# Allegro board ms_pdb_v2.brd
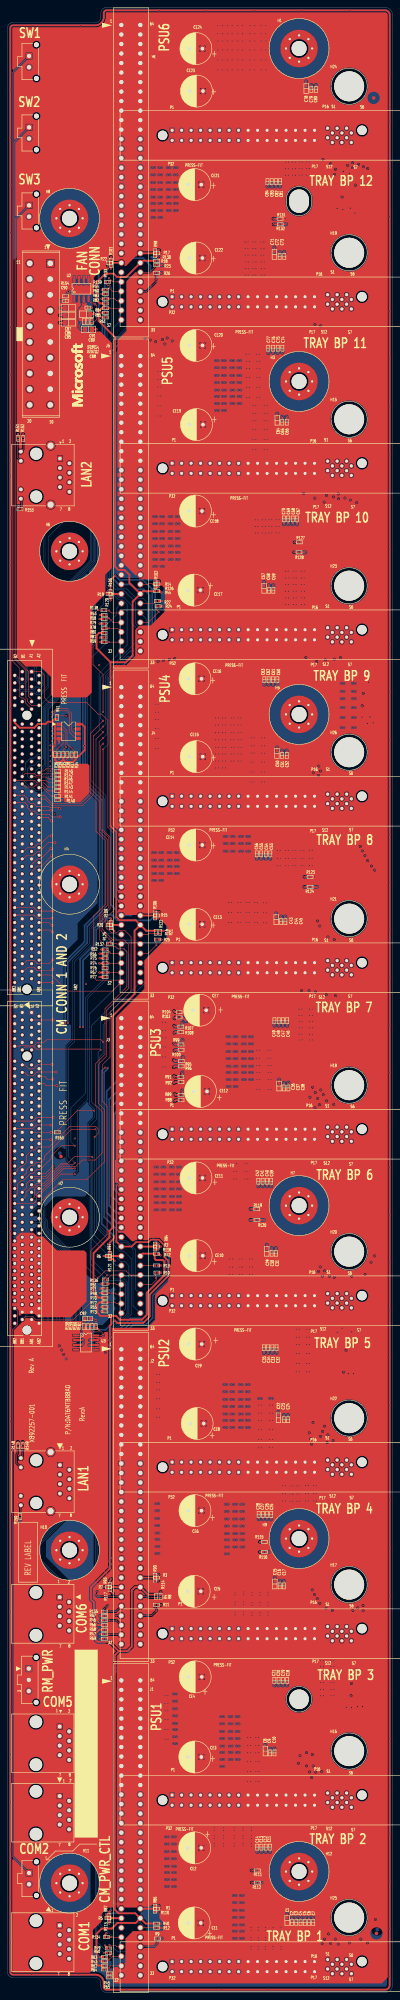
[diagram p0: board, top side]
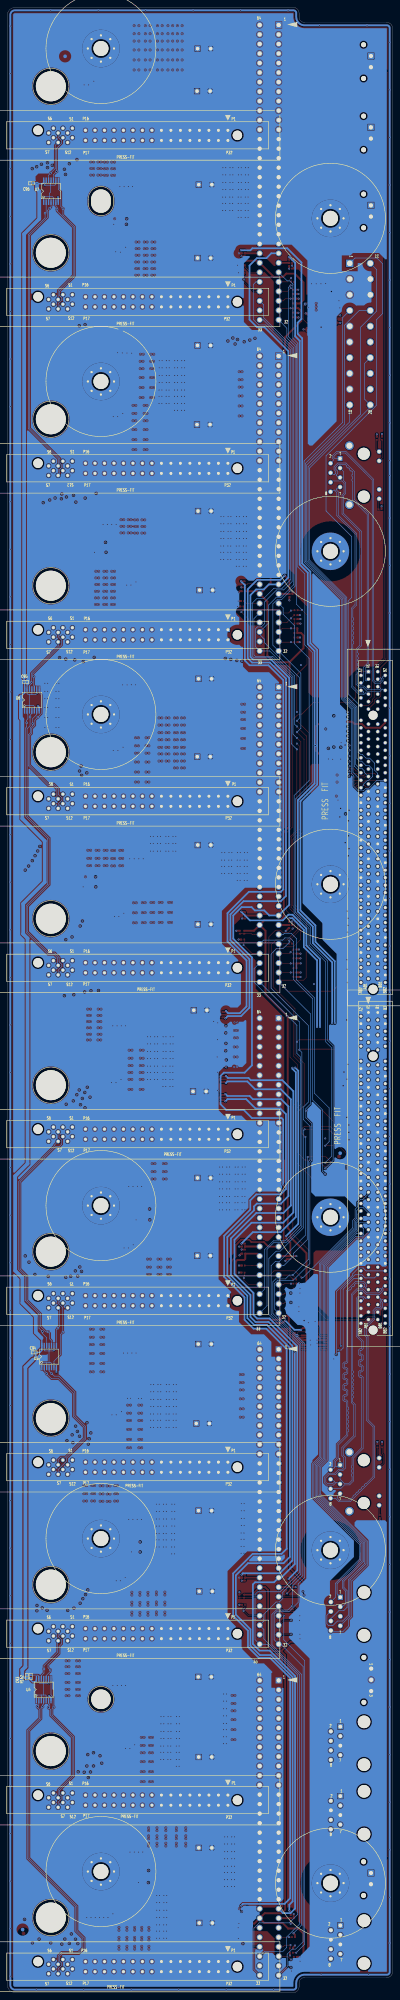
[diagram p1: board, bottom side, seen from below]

Outline 103 x 530 mm; copper layers: TOP, GND, IN1, VCC, VCC1, IN2, GND1, BOTTOM. Coordinates in mm from the lower left corner of the outline.
Outline path: 0,524.5 0,5.5 arc(0.44,4.44) 1.5,4 23.5,4 arc(24.56,3.56) 25,2.5 25,1.5 arc(25.44,0.44) 26.5,0 101,0 arc(102.41,0.59) 103,2 103,528 arc(102.41,529.41) 101,530 26.5,530 arc(25.44,529.56) 25,528.5 25,527.5 arc(24.56,526.44) 23.5,526 1.5,526 arc(0.44,525.56) 0,524.5 ; 75.4,478.8 arc(78,481.4) 80.6,478.8 80.6,477.8 arc(78,475.2) 75.4,477.8 75.4,478.8

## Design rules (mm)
net group LAN: nets LAN1_P1_P LAN1_P2_P LAN1_P4_N LAN1_P4_P
net group SMB: nets I2C_PDB_SCL I2C_PDB_SDA I2C_PSU1_SCL I2C_PSU1_SDA I2C_PSU2_SCL I2C_PSU2_SDA I2C_PSU3_SCL I2C_PSU3_SDA
net group UART: nets UART_CTS_P1_L_N UART_CTS_P2_L_N UART_CTS_P5_L_N UART_CTS_P6_L_N UART_DSR_P1_L_N UART_DSR_P2_L_N UART_DTR_P1_L_N UART_DTR_P2_L_N UART_DTR_P5_L_N UART_DTR_P6_L_N UART_RI_P5_L_N UART_RI_P6_L_N UART_RTS_P1_L_N UART_RTS_P2_L_N UART_RTS_P5_L_N UART_RTS_P6_L_N UART_RX_P1_L UART_RX_P2_L UART_RX_P5_L UART_RX_P6_L UART_TX_P1_L UART_TX_P2_L UART_TX_P5_L UART_TX_P6_L

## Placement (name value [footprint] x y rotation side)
C1  1UF  [C0603]  74.8 19.26 270 top
C2  0.1UF  [C0402]  76.12 18.75 270 top
C3  0.1UF  [C0402]  77.25 18.75 270 top
C4  0.1UF  [C0402]  78.4 18.75 270 top
C5  0.1UF  [C0402]  79.52 18.75 270 top
C6  0.1UF  [C0402]  80.66 18.75 270 top
C7  100PF  [C0402]  81.79 18.75 270 top
C8  1UF  [C0603]  68.97 64.48 270 top
C9  0.1UF  [C0402]  70.26 63.97 270 top
C10  0.1UF  [C0402]  71.42 63.97 270 top
C11  0.1UF  [C0402]  70.24 38.82 90 top
C12  0.1UF  [C0402]  69.07 38.82 90 top
C13  0.1UF  [C0402]  67.92 38.82 90 top
C14  100PF  [C0402]  66.82 38.82 90 top
C15  1UF  [C0603]  71.52 109.08 270 top
C16  0.1UF  [C0402]  72.81 108.57 270 top
C17  0.1UF  [C0402]  73.91 108.57 270 top
C18  0.1UF  [C0402]  74.8 83.34 90 top
C19  0.1UF  [C0402]  73.63 83.34 90 top
C20  0.1UF  [C0402]  72.52 83.34 90 top
C21  100PF  [C0402]  71.39 83.34 90 top
C22  1UF  [C0603]  72.48 153.43 270 top
C23  0.1UF  [C0402]  73.91 152.92 270 top
C24  0.1UF  [C0402]  75.06 152.92 270 top
C25  0.1UF  [C0402]  70.56 127.63 90 top
C26  0.1UF  [C0402]  69.44 127.63 90 top
C27  0.1UF  [C0402]  68.31 127.63 90 top
C28  100PF  [C0402]  67.19 127.63 90 top
C29  1UF  [C0603]  69.37 197.9 270 top
C30  0.1UF  [C0402]  70.66 197.39 270 top
C31  0.1UF  [C0402]  71.82 197.39 270 top
C32  0.1UF  [C0402]  71.97 172.14 90 top
C33  0.1UF  [C0402]  70.85 172.14 90 top
C34  0.1UF  [C0402]  69.73 172.14 90 top
C35  100PF  [C0402]  68.61 172.14 90 top
C36  1UF  [C0603]  72.64 242.03 270 top
C37  0.1UF  [C0402]  73.96 241.52 270 top
C38  0.1UF  [C0402]  75.15 241.52 270 top
C39  0.1UF  [C0402]  70.56 216.62 90 top
C40  0.1UF  [C0402]  69.42 216.62 90 top
C41  0.1UF  [C0402]  68.25 216.62 90 top
C42  100PF  [C0402]  67.1 216.62 90 top
C43  1UF  [C0603]  71.87 286.47 270 top
C44  0.1UF  [C0402]  73.2 285.97 270 top
C45  0.1UF  [C0402]  74.35 285.97 270 top
C46  0.1UF  [C0402]  74.83 259.45 90 top
C47  0.1UF  [C0402]  73.69 259.45 90 top
C48  0.1UF  [C0402]  72.56 259.45 90 top
C49  100PF  [C0402]  71.41 259.45 90 top
C50  1UF  [C0603]  72.09 330.84 270 top
C51  0.1UF  [C0402]  73.46 330.33 270 top
C52  0.1UF  [C0402]  74.71 330.33 270 top
C53  0.1UF  [C0402]  70.31 304.01 90 top
C54  0.1UF  [C0402]  69.11 304.01 90 top
C55  0.1UF  [C0402]  67.87 304.01 90 top
C56  100PF  [C0402]  66.69 304.01 90 top
C57  1UF  [C0603]  68.64 374.92 270 top
C58  0.1UF  [C0402]  69.98 374.41 270 top
C59  0.1UF  [C0402]  71.12 374.41 270 top
C60  0.1UF  [C0402]  72.2 350.5 90 top
C61  0.1UF  [C0402]  71 350.5 90 top
C62  0.1UF  [C0402]  69.86 350.5 90 top
C63  100PF  [C0402]  68.73 350.5 90 top
C64  1UF  [C0603]  72.16 419.8 270 top
C65  0.1UF  [C0402]  73.51 419.29 270 top
C66  0.1UF  [C0402]  74.7 419.29 270 top
C67  0.1UF  [C0402]  77.44 393.45 90 top
C68  0.1UF  [C0402]  76.3 393.45 90 top
C69  0.1UF  [C0402]  75.1 393.45 90 top
C70  100PF  [C0402]  73.93 393.45 90 top
C71  1UF  [C0603]  71.39 464.05 270 top
C72  0.1UF  [C0402]  72.8 463.54 270 top
C73  0.1UF  [C0402]  74.05 463.54 270 top
C74  0.1UF  [C0402]  73.53 439.04 90 top
C75  0.1UF  [C0402]  72.28 439.04 90 top
C76  0.1UF  [C0402]  71.04 439.04 90 top
C77  100PF  [C0402]  69.77 439.04 90 top
C78  1UF  [C0603]  79.9 508.38 270 top
C79  0.1UF  [C0402]  81.29 508.12 270 top
C80  0.1UF  [C0402]  82.5 508.12 270 top
C81  0.1UF  [C0402]  72.93 483.48 90 top
C82  0.1UF  [C0402]  71.81 483.48 90 top
C83  0.1UF  [C0402]  70.68 483.48 90 top
C84  100PF  [C0402]  69.55 483.48 90 top
C85  10UF  [C0805_H61]  16.26 445.81 0 top
C86  10UF  [C0805_H61]  16.26 447.8 0 top
C87  10UF  [C0805_H61]  16.26 449.79 0 top
C88  10UF  [C0805_H61]  21.67 444.05 180 top
C89  10UF  [C0805_H61]  21.16 448.1 180 top
C90  0.1UF  [C0402]  15.54 451.71 0 top
C91  0.1UF  [C0402]  21.51 449.86 180 top
C92  2.2UF  [C0603]  21.45 179.96 0 top
C93  0.1UF  [C0402]  97.83 84.36 270 bottom
C94  0.1UF  [C0402]  95.87 170.92 180 bottom
C95  0.1UF  [C0402]  98.16 349.95 0 bottom
C96  0.1UF  [C0402]  96.61 483.04 180 bottom
CE1  470UF  [EC138_315_433]  49.95 18.57 180 top
CE2  470UF  [EC138_315_433]  50.08 38.62 180 top
CE3  470UF  [EC138_315_433]  50.1 62.88 180 top
CE4  470UF  [EC138_315_433]  50.22 84.27 180 top
CE5  470UF  [EC138_315_433]  49.95 107.12 180 top
CE6  470UF  [EC138_315_433]  50.15 128.66 180 top
CE7  470UF  [EC138_315_433]  51.41 262.27 180 top
CE8  470UF  [EC138_315_433]  50.74 151.93 180 top
CE9  470UF  [EC138_315_433]  50.22 173.14 180 top
CE10  470UF  [EC138_315_433]  50.48 196.73 180 top
CE11  470UF  [EC138_315_433]  50.42 217.49 180 top
CE12  470UF  [EC138_315_433]  51.61 240.59 180 top
CE13  470UF  [EC138_315_433]  50.33 285.21 180 top
CE14  470UF  [EC138_315_433]  50.35 306.38 180 top
CE15  470UF  [EC138_315_433]  50.48 329.97 180 top
CE16  470UF  [EC138_315_433]  50.15 350.77 180 top
CE17  470UF  [EC138_315_433]  49.87 374.44 180 top
CE18  470UF  [EC138_315_433]  50.28 395.55 180 top
CE19  470UF  [EC138_315_433]  50.55 418.64 180 top
CE20  470UF  [EC138_315_433]  50.42 439.76 180 top
CE21  470UF  [EC138_315_433]  50.08 482.71 180 top
CE22  470UF  [EC138_315_433]  50.4 463.1 180 top
CE23  470UF  [EC138_315_433]  50.55 507.68 180 top
CE24  470UF  [EC138_315_433]  50.4 519.02 180 top
H1  GNDHOLE_8PIN  [GND_C10D4B10]  78 519.05 0 top
H2  GNDHOLE_8PIN  [GND_C10D4B10]  16.6 207 0 top
H3  GNDHOLE_8PIN  [GND_C10D4B10]  78 430.15 0 top
H4  GNDHOLE_8PIN  [GND_C10D4B10]  16.6 295.9 0 top
H5  GNDHOLE_8PIN  [GND_C10D4B10]  78 341.25 0 top
H6  GNDHOLE_8PIN  [GND_C10D4B10]  16.6 384.8 0 top
H7  GNDHOLE_8PIN  [GND_C10D4B10]  78 210.1 0 top
H8  GNDHOLE_8PIN  [GND_C10D4B10]  16.6 473.7 0 top
H9  GNDHOLE_8PIN  [GND_C10D4B10]  78 121.2 0 top
H10  GNDHOLE_8PIN  [GND_C10D4B10]  16.6 118.1 0 top
H11  GNDHOLE_8PIN  [GND_C10D4B10]  16.6 29.2 0 top
H12  GNDHOLE_8PIN  [GND_C10D4B10]  78 32.3 0 top
H13  -  [HOLE_OB5-2X6-2N]  78 478.3 0 top
H14  -  [HOLE_D5-2N]  78 78.3 0 top
H15  D8N  [HOLE_D8N]  91.4 420.06 0 top
H16  D8N  [HOLE_D8N]  91.4 64.46 0 top
H17  D8N  [HOLE_D8N]  91.4 108.91 0 top
H18  D8N  [HOLE_D8N]  91.4 242.26 0 top
H19  D8N  [HOLE_D8N]  91.4 464.51 0 top
H20  D8N  [HOLE_D8N]  91.4 197.81 0 top
H21  D8N  [HOLE_D8N]  91.4 286.71 0 top
H22  D8N  [HOLE_D8N]  91.4 153.36 0 top
H23  D8N  [HOLE_D8N]  91.4 375.61 0 top
H24  D8N  [HOLE_D8N]  91.4 508.96 0 top
H25  D8N  [HOLE_D8N]  91.4 20.01 0 top
H26  D8N  [HOLE_D8N]  91.4 331.16 0 top
J1  10046971-001LF  [CON_64D2_P2-54_LDH]  30.46 83.33 0 top
J2  10046971-001LF  [CON_64D2_P2-54_LDH]  30.46 171.73 0 top
J3  10046971-001LF  [CON_64D2_P2-54_LDH]  30.46 260.13 0 top
J4  10046971-001LF  [CON_64D2_P2-54_LDH]  30.46 348.53 0 top
J5  10046971-001LF  [CON_64D2_P2-54_LDH]  30.46 436.93 0 top
J6  10046971-001LF  [CON_64D2_P2-54_LDH]  30.46 525.33 0 top
J7  CONN44_10117936003LF  [HSD_44D2H2D_P2-54_LDH]  44.04 8.26 270 bottom
J8  CONN44_10117936003LF  [HSD_44D2H2D_P2-54_LDH]  44.04 52.71 270 bottom
J9  CONN44_10117936003LF  [HSD_44D2H2D_P2-54_LDH]  44.04 97.16 270 bottom
J10  CONN44_10117936003LF  [HSD_44D2H2D_P2-54_LDH]  44.04 141.61 270 bottom
J11  CONN44_10117936003LF  [HSD_44D2H2D_P2-54_LDH]  44.04 186.06 270 bottom
J12  CONN44_10117936003LF  [HSD_44D2H2D_P2-54_LDH]  44.04 230.51 270 bottom
J13  CONN44_10117936003LF  [HSD_44D2H2D_P2-54_LDH]  44.04 274.96 270 bottom
J14  CONN44_10117936003LF  [HSD_44D2H2D_P2-54_LDH]  44.04 319.41 270 bottom
J15  CONN44_10117936003LF  [HSD_44D2H2D_P2-54_LDH]  44.04 363.86 270 bottom
J16  CONN44_10117936003LF  [HSD_44D2H2D_P2-54_LDH]  44.04 408.31 270 bottom
J17  CONN44_10117936003LF  [HSD_44D2H2D_P2-54_LDH]  44.04 452.76 270 bottom
J18  CONN44_10117936003LF  [HSD_44D2H2D_P2-54_LDH]  44.04 497.21 270 bottom
J19  CONN8_55692841  [RJ45XBT]  13.96 17.91 270 top
J20  CONN20_39281203  [CON_PWR2X10XD]  11.44 461.69 0 top
J21  CONN8_55692841  [RJ45XBT]  13.96 52.45 270 top
J23  CONN8_55692841  [RJ45XBT]  13.96 70.99 270 top
J25  PCIEX16  [HSD_PCI-E_X16XA]  6.45 352.67 0 top
J26  PCIEX16  [HSD_PCI-E_X16XA]  6.45 261.67 0 top
J27  CONN8_55692841  [RJ45XBT]  13.96 105.54 270 top
J28  CONN12_G71B0250100EU  [RJ45XBU]  14.03 409.58 270 top
J29  CONN12_G71B0250100EU  [RJ45XBU]  14.03 140.84 270 top
J30  CONN2_43650-0217  [CON_2D1H2D_P3XA]  5.78 477.17 0 top
J31  CONN2_43650-0217  [CON_2D1H2D_P3XA]  5.78 498 0 top
J32  CONN2_43650-0217  [CON_2D1H2D_P3XA]  5.78 517.05 0 top
J33  CONN2_43650-0217  [CON_2D1H2D_P3XA]  5.78 31.91 0 top
J34  CONN3_43650-0317  [CON_3D1H2D_P3]  5.71 86.48 0 top
NOREF  -  []  41.5 495.86 0 top
NOREF#2  -  []  5.78 31.91 0 top
NOREF#3  -  []  91.4 242.26 0 top
NOREF#4  -  []  16.6 473.7 0 top
NOREF#5  -  []  -111 530 0 top
NOREF#6  -  []  91.4 64.46 0 top
NOREF#7  -  []  41.5 495.86 0 top
NOREF#8  -  []  94.84 452.76 0 top
NOREF#9  -  []  94.84 408.31 0 top
NOREF#10  -  []  -105 528 0 top
NOREF#11  -  []  16.6 384.8 0 top
NOREF#12  -  []  91.4 153.36 0 top
NOREF#13  -  []  -1 197.97 90 top
NOREF#14  -  []  101 0 90 top
NOREF#15  -  []  210.46 461.17 0 top
NOREF#16  -  []  94.84 230.51 0 top
NOREF#17  -  []  41.5 451.41 0 top
NOREF#18  -  []  94.84 274.96 0 top
NOREF#19  -  []  94.84 497.21 0 top
NOREF#20  -  []  -1 114.98 90 top
NOREF#21  -  [unnamed#2]  98.7 15.77 0 top
NOREF#22  -  []  91.4 197.81 0 top
NOREF#23  -  []  -1 32.01 90 top
NOREF#24  -  []  -1 239.48 90 top
NOREF#25  -  []  41.5 140.26 0 top
NOREF#26  -  []  16.6 29.2 0 top
NOREF#27  -  []  7.99 109.56 90 top
NOREF#28  -  []  41.5 184.71 0 top
NOREF#29  -  []  14.03 140.84 0 top
NOREF#30  -  []  13.96 105.54 0 top
NOREF#31  -  []  13.96 105.54 0 top
NOREF#32  -  []  78 519.05 0 top
NOREF#33  -  []  16.6 118.1 0 top
NOREF#34  -  []  91.4 20.01 0 top
NOREF#35  -  [unnamed#2]  14.31 223.21 0 top
NOREF#36  -  []  5.2 341.02 0 top
NOREF#37  -  []  78 478.3 0 top
NOREF#38  -  []  41.5 229.16 0 top
NOREF#39  -  []  16.6 295.9 0 top
NOREF#40  -  []  0 0 0 top
NOREF#41  -  []  41.5 6.91 0 top
NOREF#42  -  []  41.5 273.61 0 top
NOREF#43  -  []  79.57 480.38 0 top
NOREF#44  -  []  78 32.3 0 top
NOREF#45  -  []  -1 73.51 90 top
NOREF#46  -  []  91.4 420.06 0 top
NOREF#47  -  []  13.96 52.45 0 top
NOREF#48  -  []  16.6 473.7 0 top
NOREF#49  -  []  0 529.34 0 top
NOREF#50  -  []  13.96 70.99 0 top
NOREF#51  -  []  91.4 464.51 0 top
NOREF#52  -  []  -1 280.95 90 top
NOREF#53  -  []  11.44 461.69 0 top
NOREF#54  -  []  5.78 498 0 top
NOREF#55  -  []  41.5 362.51 0 top
NOREF#56  -  []  91.4 331.16 0 top
NOREF#57  -  []  -1 449.46 90 top
NOREF#58  -  []  25 528.5 0 top
NOREF#59  -  []  94.84 141.61 0 top
NOREF#60  -  []  162.67 -30.28 0 top
NOREF#61  -  []  94.84 97.16 0 top
NOREF#62  -  []  41.5 51.36 0 top
NOREF#63  -  []  -1 498.02 90 top
NOREF#64  -  []  94.84 497.21 0 top
NOREF#65  -  []  13.96 17.91 0 top
NOREF#66  -  []  -1 156.49 90 top
NOREF#67  -  []  41.5 95.81 0 top
NOREF#68  -  []  78 341.25 0 top
NOREF#69  -  []  5.78 517.05 0 top
NOREF#70  -  []  78 210.1 0 top
NOREF#71  -  []  20.1 423.59 90 top
NOREF#72  -  []  94.84 363.86 0 top
NOREF#73  -  []  -1 366.48 90 top
NOREF#74  -  []  78 519.05 0 top
NOREF#75  -  []  78 430.15 0 top
NOREF#76  -  []  41.5 406.96 0 top
NOREF#77  -  []  94.84 8.26 0 top
NOREF#78  -  []  91.4 508.96 0 top
NOREF#79  -  []  41.5 318.06 0 top
NOREF#80  -  []  16.6 207 0 top
NOREF#81  -  []  5.2 267.87 0 top
NOREF#82  -  []  91.4 508.96 0 top
NOREF#83  -  []  94 78.3 0 top
NOREF#84  -  []  0 0 0 top
NOREF#85  -  []  91.4 108.91 0 top
NOREF#86  -  []  5.2 341.02 0 top
NOREF#87  -  []  21.04 66.46 90 top
NOREF#88  -  []  94.84 186.06 0 top
NOREF#89  -  []  5.78 477.17 0 top
NOREF#90  -  []  78 121.2 0 top
NOREF#91  -  []  103 528 0 top
NOREF#92  -  []  -1 407.95 90 top
NOREF#93  -  []  -26.94 745.4 0 top
NOREF#94  -  []  91.4 375.61 0 top
NOREF#95  -  []  5.71 86.48 0 top
NOREF#96  -  []  94.84 52.71 0 top
NOREF#97  -  []  11.44 461.69 0 top
NOREF#98  -  []  14.03 409.58 0 top
NOREF#99  -  []  94.84 319.41 0 top
NOREF#100  -  []  14.03 140.84 0 top
NOREF#101  -  []  13.96 105.54 0 top
NOREF#102  -  [unnamed#2]  97.95 505.86 0 top
NOREF#103  -  []  -23.4 0 90 top
NOREF#104  -  []  91.4 286.71 0 top
NOREF#105  -  []  -1 322.46 90 top
NOREF#106  -  []  5.78 517.05 0 top
NOREF#107  -  []  0 0 0 top
NOREF#108  -  [unnamed#2]  98.95 16.81 180 bottom
NOREF#109  -  [unnamed#2]  14.01 224.1 180 bottom
NOREF#110  -  [unnamed#2]  87.59 516.96 180 bottom
R1  0  [R0402]  39.87 22.38 180 top
R2  0  [R0402]  39.86 199.17 180 top
R3  0  [R0402]  39.86 110.77 180 top
R4  22.1K  [R0402]  39.71 105.82 270 top
R5  0  [R0402]  26.85 19.86 0 top
R6  0  [R0402]  26.93 196.62 0 top
R7  0  [R0402]  26.95 108.23 0 top
R8  8.2K  [R0402]  40.96 105.82 270 top
R9  100  [R0402]  40.16 14.41 180 top
R10  100  [R0402]  39.97 192.22 180 top
R11  100  [R0402]  39.86 103.52 180 top
R12  100  [R0402]  39.85 17.31 180 top
R13  100  [R0402]  39.9 194.11 180 top
R14  0  [R0402]  39.98 375.99 180 top
R15  0  [R0402]  39.86 287.57 180 top
R16  22.1K  [R0402]  39.65 283.1 270 top
R17  0  [R0402]  39.94 464.37 180 top
R18  22.1K  [R0402]  39.87 462.37 0 top
R19  0  [R0402]  27.17 373.43 0 top
R20  0  [R0402]  27.24 285.03 0 top
R21  8.2K  [R0402]  40.86 283.1 270 top
R22  0  [R0402]  27.24 461.83 0 top
R23  8.2K  [R0402]  39.87 461.17 180 top
R24  100  [R0402]  40.3 370.1 180 top
R25  100  [R0402]  40.06 281.14 180 top
R26  100  [R0402]  39.95 459.17 180 top
R27  100  [R0402]  40.11 371.51 180 top
R34  3.3K  [R0402]  18.26 330.46 270 top
R35  3.3K  [R0402]  14.92 330.5 270 top
R36  3.3K  [R0402]  12.78 330.48 270 top
R37  100  [R0402]  17.16 330.46 270 top
R38  100  [R0402]  16.02 330.5 270 top
R39  100  [R0402]  13.85 330.48 270 top
R40  100K  [R0402]  39.82 18.41 0 top
R41  10K  [R0402]  13.27 340.46 270 top
R42  100K  [R0402]  39.8 197.27 0 top
R43  100  [R0402]  26 8.34 0 top
R44  100K  [R0402]  39.93 374.15 0 top
R45  100  [R0402]  27.28 5.1 0 top
R46  100  [R0402]  25.93 99.37 0 top
R47  100  [R0402]  25.93 95.65 0 top
R48  100  [R0402]  26.07 186.75 0 top
R49  560  [R0402]  27.05 11.76 180 top
R50  560  [R0402]  27.05 10.62 0 top
R51  560  [R0402]  26.1 189.27 180 top
R52  560  [R0402]  26.13 278.49 180 top
R53  560  [R0402]  25.87 367.77 180 top
R54  560  [R0402]  26.25 454.65 180 top
R55  100  [R0402]  26.07 183.07 0 top
R56  100  [R0402]  26.1 277.38 0 top
R57  100  [R0402]  26.1 272.35 0 top
R58  100  [R0402]  25.86 366.71 0 top
R59  100  [R0402]  25.86 360.55 0 top
R60  100  [R0402]  26.23 453.54 0 top
R61  100  [R0402]  26.23 447.25 0 top
R62  22.1K  [R0402]  26 7.19 0 top
R63  8.2K  [R0402]  26 9.51 0 top
R64  22.1K  [R0402]  25.98 6.15 0 top
R65  8.2K  [R0402]  27.28 4.03 0 top
R66  22.1K  [R0402]  25.93 98.1 0 top
R67  8.2K  [R0402]  25.93 100.59 0 top
R68  22.1K  [R0402]  25.93 96.87 0 top
R69  8.2K  [R0402]  25.93 94.46 0 top
R70  22.1K  [R0402]  26.07 185.52 0 top
R71  8.2K  [R0402]  26.07 187.95 0 top
R72  22.1K  [R0402]  26.07 184.27 0 top
R73  8.2K  [R0402]  26.07 181.85 0 top
R74  22.1K  [R0402]  26.1 274.77 0 top
R75  8.2K  [R0402]  26.1 276.12 0 top
R76  22.1K  [R0402]  26.1 273.53 0 top
R77  8.2K  [R0402]  26.1 271.15 0 top
R78  22.1K  [R0402]  25.86 364.25 0 top
R79  8.2K  [R0402]  25.86 365.5 0 top
R80  22.1K  [R0402]  25.86 363.02 0 top
R81  8.2K  [R0402]  25.86 361.78 0 top
R82  22.1K  [R0402]  26.23 450.98 0 top
R83  8.2K  [R0402]  26.23 452.26 0 top
R84  22.1K  [R0402]  26.23 449.71 0 top
R85  8.2K  [R0402]  26.23 448.49 0 top
R86  0  [R0402]  39.46 22.79 270 top
R87  0  [R0402]  27.25 20.26 270 top
R88  0  [R0402]  46.43 238.25 180 top
R89  0  [R0402]  46.41 239.67 180 top
R90  0  [R0402]  39.46 111.17 270 top
R91  0  [R0402]  46.39 244.52 180 top
R92  0  [R0402]  46.41 243.1 180 top
R93  0  [R0402]  27.35 108.63 270 top
R94  0  [R0402]  39.46 199.57 270 top
R95  0  [R0402]  46.5 248.71 180 top
R96  0  [R0402]  46.47 247.28 180 top
R97  0  [R0402]  27.33 197.03 270 top
R98  0  [R0402]  39.51 464.77 270 top
R99  0  [R0402]  46.43 253.13 180 top
R100  0  [R0402]  46.44 251.7 180 top
R101  0  [R0402]  27.64 462.23 270 top
R102  0  [R0402]  39.58 376.39 270 top
R103  0  [R0402]  45.91 260.36 180 top
R104  0  [R0402]  45.91 261.78 180 top
R105  0  [R0402]  27.58 373.83 270 top
R106  0  [R0402]  39.44 287.98 270 top
R107  0  [R0402]  46.37 257.89 180 top
R108  0  [R0402]  46.37 256.47 180 top
R109  0  [R0402]  27.64 285.43 270 top
R110  0  [R0402]  39.46 21.99 90 top
R111  0  [R0402]  66.83 32.57 180 top
R112  0  [R0402]  66.89 29.35 180 top
R113  0  [R0402]  27.24 19.46 90 top
R114  0  [R0402]  39.46 110.37 90 top
R115  0  [R0402]  68.7 120.31 180 top
R116  0  [R0402]  68.72 117.63 180 top
R117  0  [R0402]  27.35 107.83 90 top
R118  0  [R0402]  39.46 198.77 90 top
R119  0  [R0402]  66.7 209.2 180 top
R120  0  [R0402]  66.74 206.29 180 top
R121  0  [R0402]  27.33 196.23 90 top
R122  0  [R0402]  39.44 287.18 90 top
R123  0  [R0402]  80.95 297.89 180 top
R124  0  [R0402]  80.93 295.22 180 top
R125  0  [R0402]  27.64 284.63 90 top
R126  0  [R0402]  39.58 375.59 90 top
R127  0  [R0402]  78.06 387.2 180 top
R128  0  [R0402]  77.99 384.53 180 top
R129  0  [R0402]  27.58 373.03 90 top
R130  0  [R0402]  39.51 463.97 90 top
R131  0  [R0402]  72.93 473.6 180 top
R132  0  [R0402]  72.95 472.1 180 top
R133  0  [R0402]  27.64 461.43 90 top
R134  0  [R0402]  26.49 14.8 0 top
R135  0  [R0402]  26 101.69 0 top
R136  0  [R0402]  26.19 190.37 0 top
R137  0  [R0402]  27.29 280.04 0 top
R138  0  [R0402]  25.8 369.1 0 top
R139  0  [R0402]  26.73 456.75 0 top
R140  8.2K  [R0402]  13.42 318.36 180 top
R141  22.1K  [R0402]  13.39 319.44 180 top
R142  8.2K  [R0402]  13.46 325.06 180 top
R143  8.2K  [R0402]  13.46 321.89 180 top
R144  8.2K  [R0402]  13.37 320.83 180 top
R145  8.2K  [R0402]  13.43 326.15 180 top
R146  8.2K  [R0402]  13.46 324.01 180 top
R147  8.2K  [R0402]  13.44 322.97 180 top
R148  100  [R0402]  2.77 145.96 270 top
R149  100  [R0402]  4.06 145.97 270 top
R150  100  [R0402]  3.41 127.09 270 top
R151  100  [R0402]  2.83 415 270 top
R152  100  [R0402]  4.2 414.97 270 top
R153  100  [R0402]  3.33 396.06 180 top
R154  0  [R0402]  15.51 452.88 180 top
R155  0  [R0402]  20.41 446.15 90 top
R156  30.1K  [R0402]  21.44 446.15 90 top
R157  18.2K  [R0402]  22.51 446.15 270 top
R158  22.1K  [R0402]  20.39 177.8 270 top
R159  8.2K  [R0402]  21.47 177.8 90 top
R160  0  [R0402]  22.52 177.8 270 top
R161  0  [R0402]  23.59 177.8 90 top
R162  4.7K  [R0402]  96.75 84.35 270 bottom
R163  0  [R0402]  13.32 229.67 180 top
U1  M24128-BWMN6TP  [SOIC8XH]  16.35 336.73 0 top
U2  MIC39102YM  [SOIC8]  19.78 454.9 0 top
U3  TL431BCDR2G  [SOIC8]  20.98 173.54 270 top
U4  74LVC07  [TSSOP14]  93.31 80.87 180 bottom
U5  74LVC07  [TSSOP14]  91.87 169.8 180 bottom
U6  74LVC07  [TSSOP14]  96.47 345.12 180 bottom
U7  74LVC07  [TSSOP14]  91.35 480.95 180 bottom

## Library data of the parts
C1-C96 = CAP_NP
CE1-CE24 = CAPACITOR_POL
H1-H12 = GND_HOLE
H13-H26 = HOLE_N
J1-J6 = CON_2X32
J7-J18 = CONN44_10117936003LF
J19 J21 J23 J27 = CONN8_55692841
J20 = CONN20_39281203
J25 J26 = PCI_EXPRESS_X16_CONN
J28 J29 = CONN12_G71B0250100EU
J30-J33 = CONN2_436500217
J34 = CONN3_436500317
R1-R27 R34-R163 = R
U1 = M24128
U2 = MIC39102
U3 = LM431_1
U4-U7 = 74LVC07

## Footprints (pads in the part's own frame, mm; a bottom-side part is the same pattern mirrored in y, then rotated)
C0402
  rect 0.457x0.508 smd: 1(0.4,0) 2(-0.4,0)
C0603
  rect 0.813x0.711 smd: 1(0.737,0) 2(-0.737,0)
C0805_H61
  rect 1.118x1.372 smd: 1(0.95,0) 2(-0.95,0)
CON_2D1H2D_P3XA
  round 1.321 hole 1.321 unplated: (1.96,3) (1.96,-6)
  rect 1.6x1.6 hole 1.092: 1(0,0)
  round 1.6 hole 1.092: 2(0,-3)
CON_3D1H2D_P3
  round 1.321 hole 1.321 unplated: (1.96,3) (1.96,-9)
  rect 1.6x1.6 hole 1.092: 1(0,0)
  round 1.6 hole 1.092: 2(0,-3) 3(0,-6)
CON_64D2_P2-54_LDH
  rect 1.626x1.626 hole 1.118: 1(0,0)
  round 1.626 hole 1.118: 2(0,-2.54) 3(0,-5.08) 4(0,-7.62) 5(0,-10.16) 6(0,-12.7) 7(0,-15.24) 8(0,-17.78) 9(0,-20.32) 10(0,-22.86) 11(0,-25.4) 12(0,-27.94) 13(0,-30.48) 14(0,-33.02) 15(0,-35.56) 16(0,-38.1) 17(0,-40.64) 18(0,-43.18) 19(0,-45.72) 20(0,-48.26) 21(0,-50.8) 22(0,-53.34) 23(0,-55.88) 24(0,-58.42) 25(0,-60.96) 26(0,-63.5) 27(0,-66.04) 28(0,-68.58) 29(0,-71.12) 30(0,-73.66) 31(0,-76.2) 32(0,-78.74) 33(5.08,-78.74) 34(5.08,-76.2) 35(5.08,-73.66) 36(5.08,-71.12) 37(5.08,-68.58) 38(5.08,-66.04) 39(5.08,-63.5) 40(5.08,-60.96) 41(5.08,-58.42) 42(5.08,-55.88) 43(5.08,-53.34) 44(5.08,-50.8) 45(5.08,-48.26) 46(5.08,-45.72) 47(5.08,-43.18) 48(5.08,-40.64) 49(5.08,-38.1) 50(5.08,-35.56) 51(5.08,-33.02) 52(5.08,-30.48) 53(5.08,-27.94) 54(5.08,-25.4) 55(5.08,-22.86) 56(5.08,-20.32) 57(5.08,-17.78) 58(5.08,-15.24) 59(5.08,-12.7) 60(5.08,-10.16) 61(5.08,-7.62) 62(5.08,-5.08) 63(5.08,-2.54) 64(5.08,0)
CON_PWR2X10XD
  rect 1.956x1.956 hole 1.448: 1(0,0)
  round 1.956 hole 1.448: 2(0,-4.2) 3(0,-8.4) 4(0,-12.6) 5(0,-16.8) 6(0,-21) 7(0,-25.2) 8(0,-29.4) 9(0,-33.6) 10(0,-37.8) 11(-5.5,0) 12(-5.5,-4.2) 13(-5.5,-8.4) 14(-5.5,-12.6) 15(-5.5,-16.8) 16(-5.5,-21) 17(-5.5,-25.2) 18(-5.5,-29.4) 19(-5.5,-33.6) 20(-5.5,-37.8)
EC138_315_433
  rect 1.397x1.397 hole 0.914: 1(-1.75,0)
  round 1.397 hole 0.914: 2(1.75,0)
GND_C10D4B10
  round 4.013 hole 4.013 unplated: (0,0)
  round 0.762 hole 0.559: 2(0,3.5) 3(-2.5,2.5) 4(-3.5,0) 5(-2.5,-2.5) 6(0,-3.5) 7(2.5,-2.5) 8(3.5,0) 9(2.5,2.5)
HOLE_D5-2N
  round 5.207 hole 5.207 unplated: (0,0)
HOLE_D8N
  round 8.001 hole 8.001 unplated: (0,0)
HOLE_OB5-2X6-2N
  oval 5.207x6.198 hole 5.207x6.198 unplated: (0,0)
HSD_44D2H2D_P2-54_LDH
  round 2.515 hole 2.515 unplated: (0,-50.8) (1.35,2.54)
  rect 1.168x1.168 hole 0.762: P1(0,0)
  round 1.168 hole 0.762: P2(0,-2.54) P3(0,-5.08) P4(0,-7.62) P5(0,-10.16) P6(0,-12.7) P7(0,-15.24) P8(0,-17.78) P9(0,-20.32) P10(0,-22.86) P11(0,-25.4) P12(0,-27.94) P13(0,-30.48) P14(0,-33.02) P15(0,-35.56) P16(0,-38.1) P17(2.7,-38.1) P18(2.7,-35.56) P19(2.7,-33.02) P20(2.7,-30.48) P21(2.7,-27.94) P22(2.7,-25.4) P23(2.7,-22.86) P24(2.7,-20.32) P25(2.7,-17.78) P26(2.7,-15.24) P27(2.7,-12.7) P28(2.7,-10.16) P29(2.7,-7.62) P30(2.7,-5.08) P31(2.7,-2.54) P32(2.7,0) S1(-0.555,-41.6) S2(0.715,-42.87) S3(-0.555,-44.14) S4(0.715,-45.41) S5(-0.555,-46.68) S6(0.715,-47.95) S7(3.255,-47.95) S8(1.985,-46.68) S9(3.255,-45.41) S10(1.985,-44.14) S11(3.255,-42.87) S12(1.985,-41.6)
HSD_PCI-E_X16XA
  round 2.413 hole 2.413 unplated: (-1.25,-11.65) (-1.25,-84.8)
  rect 1.016x1.016 hole 0.711: A1(0,0)
  round 1.016 hole 0.711: A2(2,-1) A3(0,-2) A4(2,-3) A5(0,-4) A6(2,-5) A7(0,-6) A8(2,-7) A9(0,-8) A10(2,-9) A11(0,-10) A12(2,-13) A13(0,-14) A14(2,-15) A15(0,-16) A16(2,-17) A17(0,-18) A18(2,-19) A19(0,-20) A20(2,-21) A21(0,-22) A22(2,-23) A23(0,-24) A24(2,-25) A25(0,-26) A26(2,-27) A27(0,-28) A28(2,-29) A29(0,-30) A30(2,-31) A31(0,-32) A32(2,-33) A33(0,-34) A34(2,-35) A35(0,-36) A36(2,-37) A37(0,-38) A38(2,-39) A39(0,-40) A40(2,-41) A41(0,-42) A42(2,-43) A43(0,-44) A44(2,-45) A45(0,-46) A46(2,-47) A47(0,-48) A48(2,-49) A49(0,-50) A50(2,-51) A51(0,-52) A52(2,-53) A53(0,-54) A54(2,-55) A55(0,-56) A56(2,-57) A57(0,-58) A58(2,-59) A59(0,-60) A60(2,-61) A61(0,-62) A62(2,-63) A63(0,-64) A64(2,-65) A65(0,-66) A66(2,-67) A67(0,-68) A68(2,-69) A69(0,-70) A70(2,-71) A71(0,-72) A72(2,-73) A73(0,-74) A74(2,-75) A75(0,-76) A76(2,-77) A77(0,-78) A78(2,-79) A79(0,-80) A80(2,-81) A81(0,-82) A82(2,-83) B1(-2.5,0) B2(-4.5,-1) B3(-2.5,-2) B4(-4.5,-3) B5(-2.5,-4) B6(-4.5,-5) B7(-2.5,-6) B8(-4.5,-7) B9(-2.5,-8) B10(-4.5,-9) B11(-2.5,-10) B12(-4.5,-13) B13(-2.5,-14) B14(-4.5,-15) B15(-2.5,-16) B16(-4.5,-17) B17(-2.5,-18) B18(-4.5,-19) B19(-2.5,-20) B20(-4.5,-21) B21(-2.5,-22) B22(-4.5,-23) B23(-2.5,-24) B24(-4.5,-25) B25(-2.5,-26) B26(-4.5,-27) B27(-2.5,-28) B28(-4.5,-29) B29(-2.5,-30) B30(-4.5,-31) B31(-2.5,-32) B32(-4.5,-33) B33(-2.5,-34) B34(-4.5,-35) B35(-2.5,-36) B36(-4.5,-37) B37(-2.5,-38) B38(-4.5,-39) B39(-2.5,-40) B40(-4.5,-41) B41(-2.5,-42) B42(-4.5,-43) B43(-2.5,-44) B44(-4.5,-45) B45(-2.5,-46) B46(-4.5,-47) B47(-2.5,-48) B48(-4.5,-49) B49(-2.5,-50) B50(-4.5,-51) B51(-2.5,-52) B52(-4.5,-53) B53(-2.5,-54) B54(-4.5,-55) B55(-2.5,-56) B56(-4.5,-57) B57(-2.5,-58) B58(-4.5,-59) B59(-2.5,-60) B60(-4.5,-61) B61(-2.5,-62) B62(-4.5,-63) B63(-2.5,-64) B64(-4.5,-65) B65(-2.5,-66) B66(-4.5,-67) B67(-2.5,-68) B68(-4.5,-69) B69(-2.5,-70) B70(-4.5,-71) B71(-2.5,-72) B72(-4.5,-73) B73(-2.5,-74) B74(-4.5,-75) B75(-2.5,-76) B76(-4.5,-77) B77(-2.5,-78) B78(-4.5,-79) B79(-2.5,-80) B80(-4.5,-81) B81(-2.5,-82) B82(-4.5,-83)
R0402
  rect 0.457x0.508 smd: 1(0.4,0) 2(-0.4,0)
RJ45XBT
  round 3.353 hole 3.353 unplated: (-1.27,-6.35) (10.16,-6.35)
  rect 1.397x1.397 hole 0.991: 1(0,0)
  round 1.397 hole 0.991: 2(1.27,2.54) 3(2.54,0) 4(3.81,2.54) 5(5.08,0) 6(6.35,2.54) 7(7.62,0) 8(8.89,2.54)
RJ45XBU
  round 3.2 hole 3.2 unplated: (-1.27,-6.35) (10.16,-6.35)
  rect 1.321x1.321 hole 0.914: 1(0,0)
  round 1.321 hole 0.914: 2(1.27,2.54) 3(2.54,0) 4(3.81,2.54) 5(5.08,0) 6(6.35,2.54) 7(7.62,0) 8(8.89,2.54) 9(-1.855,-10.46) 10(0.635,-10.46) 11(8.255,-10.46) 12(10.745,-10.46)
  round 2.362 hole 1.6: G1(-3.43,-2.5) G2(12.32,-2.5)
SOIC8
  rect 0.559x1.727 smd: 1(-1.905,-2.642) 2(-0.635,-2.642) 3(0.635,-2.642) 4(1.905,-2.642) 5(1.905,2.642) 6(0.635,2.642) 7(-0.635,2.642) 8(-1.905,2.642)
SOIC8XH
  rect 1.27x0.889 smd: 1(-2.6,1.905) 2(-2.6,0.635) 3(-2.6,-0.635) 4(-2.6,-1.905) 5(2.6,-1.905) 6(2.6,-0.635) 7(2.6,0.635) 8(2.6,1.905)
TSSOP14
  rect 0.356x1.499 smd: 1(-1.95,-2.921) 2(-1.3,-2.921) 3(-0.65,-2.921) 4(0,-2.921) 5(0.65,-2.921) 6(1.3,-2.921) 7(1.95,-2.921) 8(1.95,2.921) 9(1.3,2.921) 10(0.65,2.921) 11(0,2.921) 12(-0.65,2.921) 13(-1.3,2.921) 14(-1.95,2.921)
unnamed#2
  round 0.991 smd: 1(0,0)

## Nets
GND: C1.2 C2.2 C3.2 C4.2 C5.2 C6.2 C7.2 C8.2 C9.2 C10.2 C11.2 C12.2 C13.2 C14.2 C15.2 C16.2 C17.2 C18.2 C19.2 C20.2 C21.2 C22.2 C23.2 C24.2 C25.2 C26.2 C27.2 C28.2 C29.2 C30.2 C31.2 C32.2 C33.2 C34.2 C35.2 C36.2 C37.2 C38.2 C39.2 C40.2 C41.2 C42.2 C43.2 C44.2 C45.2 C46.2 C47.2 C48.2 C49.2 C50.2 C51.2 C52.2 C53.2 C54.2 C55.2 C56.2 C57.2 C58.2 C59.2 C60.2 C61.2 C62.2 C63.2 C64.2 C65.2 C66.2 C67.2 C68.2 C69.2 C70.2 C71.2 C72.2 C73.2 C74.2 C75.2 C76.2 C77.2 C78.2 C79.2 C80.2 C81.2 C82.2 C83.2 C84.2 C85.2 C86.2 C87.2 C88.2 C89.2 C90.2 C91.2 C92.2 C93.2 C94.2 C95.2 C96.2 CE1.2 CE2.2 CE3.2 CE4.2 CE5.2 CE6.2 CE7.2 CE8.2 CE9.2 CE10.2 CE11.2 CE12.2 CE13.2 CE14.2 CE15.2 CE16.2 CE17.2 CE18.2 CE19.2 CE20.2 CE21.2 CE22.2 CE23.2 CE24.2 H1.2(GND2) H1.3(GND3) H1.4(GND4) H1.5(GND5) H1.6(GND6) H1.7(GND7) H1.8(GND8) H1.9(GND9) H2.2(GND2) H2.3(GND3) H2.4(GND4) H2.5(GND5) H2.6(GND6) H2.7(GND7) H2.8(GND8) H2.9(GND9) H3.2(GND2) H3.3(GND3) H3.4(GND4) H3.5(GND5) H3.6(GND6) H3.7(GND7) H3.8(GND8) H3.9(GND9) H4.2(GND2) H4.3(GND3) H4.4(GND4) H4.5(GND5) H4.6(GND6) H4.7(GND7) H4.8(GND8) H4.9(GND9) H5.2(GND2) H5.3(GND3) H5.4(GND4) H5.5(GND5) H5.6(GND6) H5.7(GND7) H5.8(GND8) H5.9(GND9) H6.2(GND2) H6.3(GND3) H6.4(GND4) H6.5(GND5) H6.6(GND6) H6.7(GND7) H6.8(GND8) H6.9(GND9) H7.2(GND2) H7.3(GND3) H7.4(GND4) H7.5(GND5) H7.6(GND6) H7.7(GND7) H7.8(GND8) H7.9(GND9) H8.2(GND2) H8.3(GND3) H8.4(GND4) H8.5(GND5) H8.6(GND6) H8.7(GND7) H8.8(GND8) H8.9(GND9) H9.2(GND2) H9.3(GND3) H9.4(GND4) H9.5(GND5) H9.6(GND6) H9.7(GND7) H9.8(GND8) H9.9(GND9) H10.2(GND2) H10.3(GND3) H10.4(GND4) H10.5(GND5) H10.6(GND6) H10.7(GND7) H10.8(GND8) H10.9(GND9) H11.2(GND2) H11.3(GND3) H11.4(GND4) H11.5(GND5) H11.6(GND6) H11.7(GND7) H11.8(GND8) H11.9(GND9) H12.2(GND2) H12.3(GND3) H12.4(GND4) H12.5(GND5) H12.6(GND6) H12.7(GND7) H12.8(GND8) H12.9(GND9) J1.13(RTN1) J1.14(RTN2) J1.15(RTN3) J1.16(RTN4) J1.17(RTN5) J1.18(RTN6) J1.19(RTN7) J1.20(RTN8) J1.21(RTN9) J1.22(RTN10) J1.23(RTN11) J1.24(RTN12) J1.41(RTN13) J1.42(RTN14) J1.43(RTN15) J1.44(RTN16) J1.45(RTN17) J1.46(RTN18) J1.47(RTN19) J1.48(RTN20) J1.49(RTN21) J1.50(RTN22) J1.51(RTN23) J1.52(RTN24) J2.13(RTN1) J2.14(RTN2) J2.15(RTN3) J2.16(RTN4) J2.17(RTN5) J2.18(RTN6) J2.19(RTN7) J2.20(RTN8) J2.21(RTN9) J2.22(RTN10) J2.23(RTN11) J2.24(RTN12) J2.41(RTN13) J2.42(RTN14) J2.43(RTN15) J2.44(RTN16) J2.45(RTN17) J2.46(RTN18) J2.47(RTN19) J2.48(RTN20) J2.49(RTN21) J2.50(RTN22) J2.51(RTN23) J2.52(RTN24) J3.13(RTN1) J3.14(RTN2) J3.15(RTN3) J3.16(RTN4) J3.17(RTN5) J3.18(RTN6) J3.19(RTN7) J3.20(RTN8) J3.21(RTN9) J3.22(RTN10) J3.23(RTN11) J3.24(RTN12) J3.41(RTN13) J3.42(RTN14) J3.43(RTN15) J3.44(RTN16) J3.45(RTN17) J3.46(RTN18) J3.47(RTN19) J3.48(RTN20) J3.49(RTN21) J3.50(RTN22) J3.51(RTN23) J3.52(RTN24) J4.13(RTN1) J4.14(RTN2) J4.15(RTN3) J4.16(RTN4) J4.17(RTN5) J4.18(RTN6) J4.19(RTN7) J4.20(RTN8) J4.21(RTN9) J4.22(RTN10) J4.23(RTN11) J4.24(RTN12) J4.41(RTN13) J4.42(RTN14) J4.43(RTN15) J4.44(RTN16) J4.45(RTN17) J4.46(RTN18) J4.47(RTN19) J4.48(RTN20) J4.49(RTN21) J4.50(RTN22) J4.51(RTN23) J4.52(RTN24) J5.13(RTN1) J5.14(RTN2) J5.15(RTN3) J5.16(RTN4) J5.17(RTN5) J5.18(RTN6) J5.19(RTN7) J5.20(RTN8) J5.21(RTN9) J5.22(RTN10) J5.23(RTN11) J5.24(RTN12) J5.41(RTN13) J5.42(RTN14) J5.43(RTN15) J5.44(RTN16) J5.45(RTN17) J5.46(RTN18) J5.47(RTN19) J5.48(RTN20) J5.49(RTN21) J5.50(RTN22) J5.51(RTN23) J5.52(RTN24) J6.13(RTN1) J6.14(RTN2) J6.15(RTN3) J6.16(RTN4) J6.17(RTN5) J6.18(RTN6) J6.19(RTN7) J6.20(RTN8) J6.21(RTN9) J6.22(RTN10) J6.23(RTN11) J6.24(RTN12) J6.41(RTN13) J6.42(RTN14) J6.43(RTN15) J6.44(RTN16) J6.45(RTN17) J6.46(RTN18) J6.47(RTN19) J6.48(RTN20) J6.49(RTN21) J6.50(RTN22) J6.51(RTN23) J6.52(RTN24) J7.P1 J7.P2 J7.P3 J7.P4 J7.P5 J7.P6 J7.P7 J7.P8 J7.P25 J7.P26 J7.P27 J7.P28 J7.P29 J7.P30 J7.P31 J7.P32 J8.P1 J8.P2 J8.P3 J8.P4 J8.P5 J8.P6 J8.P7 J8.P8 J8.P25 J8.P26 J8.P27 J8.P28 J8.P29 J8.P30 J8.P31 J8.P32 J9.P1 J9.P2 J9.P3 J9.P4 J9.P5 J9.P6 J9.P7 J9.P8 J9.P25 J9.P26 J9.P27 J9.P28 J9.P29 J9.P30 J9.P31 J9.P32 J10.P1 J10.P2 J10.P3 J10.P4 J10.P5 J10.P6 J10.P7 J10.P8 J10.P25 J10.P26 J10.P27 J10.P28 J10.P29 J10.P30 J10.P31 J10.P32 J11.P1 J11.P2 J11.P3 J11.P4 J11.P5 J11.P6 J11.P7 J11.P8 J11.P25 J11.P26 J11.P27 J11.P28 J11.P29 J11.P30 J11.P31 J11.P32 J12.P1 J12.P2 J12.P3 J12.P4 J12.P5 J12.P6 J12.P7 J12.P8 J12.P25 J12.P26 J12.P27 J12.P28 J12.P29 J12.P30 J12.P31 J12.P32 J13.P1 J13.P2 J13.P3 J13.P4 J13.P5 J13.P6 J13.P7 J13.P8 J13.P25 J13.P26 J13.P27 J13.P28 J13.P29 J13.P30 J13.P31 J13.P32 J14.P1 J14.P2 J14.P3 J14.P4 J14.P5 J14.P6 J14.P7 J14.P8 J14.P25 J14.P26 J14.P27 J14.P28 J14.P29 J14.P30 J14.P31 J14.P32 J15.P1 J15.P2 J15.P3 J15.P4 J15.P5 J15.P6 J15.P7 J15.P8 J15.P25 J15.P26 J15.P27 J15.P28 J15.P29 J15.P30 J15.P31 J15.P32 J16.P1 J16.P2 J16.P3 J16.P4 J16.P5 J16.P6 J16.P7 J16.P8 J16.P25 J16.P26 J16.P27 J16.P28 J16.P29 J16.P30 J16.P31 J16.P32 J17.P1 J17.P2 J17.P3 J17.P4 J17.P5 J17.P6 J17.P7 J17.P8 J17.P25 J17.P26 J17.P27 J17.P28 J17.P29 J17.P30 J17.P31 J17.P32 J18.P1 J18.P2 J18.P3 J18.P4 J18.P5 J18.P6 J18.P7 J18.P8 J18.P25 J18.P26 J18.P27 J18.P28 J18.P29 J18.P30 J18.P31 J18.P32 J19.4(LAN4) J19.5(LAN5) J20.12 J20.13 J20.15 J20.16 J20.18 J20.19 J21.4(LAN4) J21.5(LAN5) J23.5(LAN5) J25.A2(12V_4) J25.A5(JTAG2) J25.A8(JTAG5) J25.A17(HSIP0-) J25.A25(HSIP2+) J25.A29(HSIP3+) J25.A31(GND44) J25.A34(GND45) J25.A39(HSIP5+) J25.A44(HSIP6-) J25.A49(GND52) J25.A54(GND54) J25.A59(GND57) J25.A64(HSIP11+) J25.A69(HSIP12-) J25.A74(GND63) J25.A79(GND66) J25.B1(12V_1) J25.B4(GND1) J25.B7(GND2) J25.B8(3.3V_1) J25.B9(JTAG1) J25.B18(GND5) J25.B26(GND9) J25.B30(RSVD2) J25.B35(GND12) J25.B40(GND15) J25.B45(HSOP7+) J25.B50(HSOP8+) J25.B55(HSOP9-) J25.B60(GND24) J25.B65(GND27) J25.B70(HSOP13+) J25.B75(HSOP14-) J25.B80(GND34) J26.A1(PRSNT1_N) J26.A4(GND35) J26.A7(JTAG4) J26.A14(REFCLK-) J26.A19(RSVD4) J26.A24(GND41) J26.A29(HSIP3+) J26.A34(GND45) J26.A39(HSIP5+) J26.A44(HSIP6-) J26.A51(GND53) J26.A59(GND57) J26.A66(GND60) J26.A71(GND62) J26.A74(GND63) J26.A77(HSIP14-) J26.B1(12V_1) J26.B4(GND1) J26.B9(JTAG1) J26.B16(GND4) J26.B21(GND6) J26.B26(GND9) J26.B31(PRSNT2_N-2) J26.B36(GND13) J26.B41(HSOP6+) J26.B44(GND17) J26.B51(HSOP8-) J26.B59(HSOP10-) J26.B66(HSOP12+) J26.B71(HSOP13-) J26.B74(HSOP14+) J26.B77(GND33) J27.5(LAN5) J28.G1(A3) J28.G2(A4) J29.G1(A3) J29.G2(A4) J30.2 J31.2 J32.2 J33.2 J34.1 J34.3 R5.2 R6.2 R7.2 R8.2 R9.2 R10.2 R11.2 R12.2 R13.2 R19.2 R20.2 R21.2 R22.2 R23.2 R24.2 R25.2 R26.2 R27.2 R37.1 R38.1 R39.1 R40.1 R42.1 R43.2 R44.1 R45.2 R46.2 R47.2 R48.2 R49.1 R50.1 R51.1 R52.1 R53.1 R54.1 R55.2 R56.2 R57.2 R58.2 R59.2 R60.2 R61.2 R63.2 R65.2 R67.2 R69.2 R71.2 R73.2 R75.2 R77.2 R79.2 R81.2 R83.2 R85.2 R89.2 R91.2 R95.2 R99.2 R103.2 R107.2 R112.2 R116.2 R120.2 R124.2 R128.2 R132.2 R140.2 R148.2 R149.2 R150.1 R151.2 R152.2 R153.1 R157.2 R160.2 U1.4(VSS) U2.5(GND#5) U2.6(GND#6) U2.7(GND#7) U2.8(GND#8) U3.2(A1) U3.3(A2) U3.6(A3) U3.7(A4) U4.7(GND) U5.7(GND) U6.7(GND) U7.7(GND)
GND3: J25.B13(GND3)
GND4: J25.B16(GND4)
GND6: J25.B21(GND6)
GND7: J25.B22(GND7)
GND8: J25.B25(GND8)
GND28: J26.B68(GND28)
GND29: J26.B69(GND29)
GND36: J25.A12(GND36)
GND37: J25.A15(GND37)
GND38: J25.A18(GND38)
GND39: J25.A20(GND39)
GND40: J25.A23(GND40)
GND41: J25.A24(GND41)
GND61: J26.A70(GND61)
P3V3: J25.B12(RSVD1) R34.1 R35.1 R36.1 R41.1 U1.8(VCC)
P3V3_BUF: C89.1 C91.1 C93.1 C94.1 C95.1 C96.1 R155.1 R156.1 R162.1 U2.3(OUT) U4.14(VCC) U5.14(VCC) U6.14(VCC) U7.14(VCC)
P12V: C1.1 C2.1 C3.1 C4.1 C5.1 C6.1 C7.1 C8.1 C9.1 C10.1 C11.1 C12.1 C13.1 C14.1 C15.1 C16.1 C17.1 C18.1 C19.1 C20.1 C21.1 C22.1 C23.1 C24.1 C25.1 C26.1 C27.1 C28.1 C29.1 C30.1 C31.1 C32.1 C33.1 C34.1 C35.1 C36.1 C37.1 C38.1 C39.1 C40.1 C41.1 C42.1 C43.1 C44.1 C45.1 C46.1 C47.1 C48.1 C49.1 C50.1 C51.1 C52.1 C53.1 C54.1 C55.1 C56.1 C57.1 C58.1 C59.1 C60.1 C61.1 C62.1 C63.1 C64.1 C65.1 C66.1 C67.1 C68.1 C69.1 C70.1 C71.1 C72.1 C73.1 C74.1 C75.1 C76.1 C77.1 C78.1 C79.1 C80.1 C81.1 C82.1 C83.1 C84.1 C85.1 C86.1 C87.1 C90.1 CE1.1 CE2.1 CE3.1 CE4.1 CE5.1 CE6.1 CE7.1 CE8.1 CE9.1 CE10.1 CE11.1 CE12.1 CE13.1 CE14.1 CE15.1 CE16.1 CE17.1 CE18.1 CE19.1 CE20.1 CE21.1 CE22.1 CE23.1 CE24.1 J1.1(+12V_1) J1.2(+12V_2) J1.3(+12V_3) J1.4(+12V_4) J1.5(+12V_5) J1.6(+12V_6) J1.7(+12V_7) J1.8(+12V_8) J1.9(+12V_9) J1.10(+12V_10) J1.11(+12V_11) J1.12(+12V_12) J1.53(+12V_13) J1.54(+12V_14) J1.55(+12V_15) J1.56(+12V_16) J1.57(+12V_17) J1.58(+12V_18) J1.59(+12V_19) J1.60(+12V_20) J1.61(+12V_21) J1.62(+12V_22) J1.63(+12V_23) J1.64(+12V_24) J2.1(+12V_1) J2.2(+12V_2) J2.3(+12V_3) J2.4(+12V_4) J2.5(+12V_5) J2.6(+12V_6) J2.7(+12V_7) J2.8(+12V_8) J2.9(+12V_9) J2.10(+12V_10) J2.11(+12V_11) J2.12(+12V_12) J2.53(+12V_13) J2.54(+12V_14) J2.55(+12V_15) J2.56(+12V_16) J2.57(+12V_17) J2.58(+12V_18) J2.59(+12V_19) J2.60(+12V_20) J2.61(+12V_21) J2.62(+12V_22) J2.63(+12V_23) J2.64(+12V_24) J3.1(+12V_1) J3.2(+12V_2) J3.3(+12V_3) J3.4(+12V_4) J3.5(+12V_5) J3.6(+12V_6) J3.7(+12V_7) J3.8(+12V_8) J3.9(+12V_9) J3.10(+12V_10) J3.11(+12V_11) J3.12(+12V_12) J3.53(+12V_13) J3.54(+12V_14) J3.55(+12V_15) J3.56(+12V_16) J3.57(+12V_17) J3.58(+12V_18) J3.59(+12V_19) J3.60(+12V_20) J3.61(+12V_21) J3.62(+12V_22) J3.63(+12V_23) J3.64(+12V_24) J4.1(+12V_1) J4.2(+12V_2) J4.3(+12V_3) J4.4(+12V_4) J4.5(+12V_5) J4.6(+12V_6) J4.7(+12V_7) J4.8(+12V_8) J4.9(+12V_9) J4.10(+12V_10) J4.11(+12V_11) J4.12(+12V_12) J4.53(+12V_13) J4.54(+12V_14) J4.55(+12V_15) J4.56(+12V_16) J4.57(+12V_17) J4.58(+12V_18) J4.59(+12V_19) J4.60(+12V_20) J4.61(+12V_21) J4.62(+12V_22) J4.63(+12V_23) J4.64(+12V_24) J5.1(+12V_1) J5.2(+12V_2) J5.3(+12V_3) J5.4(+12V_4) J5.5(+12V_5) J5.6(+12V_6) J5.7(+12V_7) J5.8(+12V_8) J5.9(+12V_9) J5.10(+12V_10) J5.11(+12V_11) J5.12(+12V_12) J5.53(+12V_13) J5.54(+12V_14) J5.55(+12V_15) J5.56(+12V_16) J5.57(+12V_17) J5.58(+12V_18) J5.59(+12V_19) J5.60(+12V_20) J5.61(+12V_21) J5.62(+12V_22) J5.63(+12V_23) J5.64(+12V_24) J6.1(+12V_1) J6.2(+12V_2) J6.3(+12V_3) J6.4(+12V_4) J6.5(+12V_5) J6.6(+12V_6) J6.7(+12V_7) J6.8(+12V_8) J6.9(+12V_9) J6.10(+12V_10) J6.11(+12V_11) J6.12(+12V_12) J6.53(+12V_13) J6.54(+12V_14) J6.55(+12V_15) J6.56(+12V_16) J6.57(+12V_17) J6.58(+12V_18) J6.59(+12V_19) J6.60(+12V_20) J6.61(+12V_21) J6.62(+12V_22) J6.63(+12V_23) J6.64(+12V_24) J7.P9 J7.P10 J7.P11 J7.P12 J7.P13 J7.P14 J7.P15 J7.P16 J7.P17 J7.P18 J7.P19 J7.P20 J7.P21 J7.P22 J7.P23 J7.P24 J8.P9 J8.P10 J8.P11 J8.P12 J8.P13 J8.P14 J8.P15 J8.P16 J8.P17 J8.P18 J8.P19 J8.P20 J8.P21 J8.P22 J8.P23 J8.P24 J9.P9 J9.P10 J9.P11 J9.P12 J9.P13 J9.P14 J9.P15 J9.P16 J9.P17 J9.P18 J9.P19 J9.P20 J9.P21 J9.P22 J9.P23 J9.P24 J10.P9 J10.P10 J10.P11 J10.P12 J10.P13 J10.P14 J10.P15 J10.P16 J10.P17 J10.P18 J10.P19 J10.P20 J10.P21 J10.P22 J10.P23 J10.P24 J11.P9 J11.P10 J11.P11 J11.P12 J11.P13 J11.P14 J11.P15 J11.P16 J11.P17 J11.P18 J11.P19 J11.P20 J11.P21 J11.P22 J11.P23 J11.P24 J12.P9 J12.P10 J12.P11 J12.P12 J12.P13 J12.P14 J12.P15 J12.P16 J12.P17 J12.P18 J12.P19 J12.P20 J12.P21 J12.P22 J12.P23 J12.P24 J13.P9 J13.P10 J13.P11 J13.P12 J13.P13 J13.P14 J13.P15 J13.P16 J13.P17 J13.P18 J13.P19 J13.P20 J13.P21 J13.P22 J13.P23 J13.P24 J14.P9 J14.P10 J14.P11 J14.P12 J14.P13 J14.P14 J14.P15 J14.P16 J14.P17 J14.P18 J14.P19 J14.P20 J14.P21 J14.P22 J14.P23 J14.P24 J15.P9 J15.P10 J15.P11 J15.P12 J15.P13 J15.P14 J15.P15 J15.P16 J15.P17 J15.P18 J15.P19 J15.P20 J15.P21 J15.P22 J15.P23 J15.P24 J16.P9 J16.P10 J16.P11 J16.P12 J16.P13 J16.P14 J16.P15 J16.P16 J16.P17 J16.P18 J16.P19 J16.P20 J16.P21 J16.P22 J16.P23 J16.P24 J17.P9 J17.P10 J17.P11 J17.P12 J17.P13 J17.P14 J17.P15 J17.P16 J17.P17 J17.P18 J17.P19 J17.P20 J17.P21 J17.P22 J17.P23 J17.P24 J18.P9 J18.P10 J18.P11 J18.P12 J18.P13 J18.P14 J18.P15 J18.P16 J18.P17 J18.P18 J18.P19 J18.P20 J18.P21 J18.P22 J18.P23 J18.P24 J20.2 J20.3 J20.5 J20.6 J20.8 J20.9 J26.A78(GND65) J26.A79(GND66) J26.A80(HSIP15+) J26.A81(HSIP15-) J26.A82(GND67) J26.B79(HSOP15-) J26.B80(GND34) J26.B82(RSVD3) J34.2 R1.2 R2.2 R3.2 R14.2 R15.2 R17.2 R88.2 R92.2 R96.2 R100.2 R104.2 R108.2 R111.2 R115.2 R119.2 R123.2 R127.2 R131.2 R141.2 R142.2 R143.2 R144.2 R145.2 R146.2 R147.2 R154.1 R158.1 U2.2(IN)
P12V_STBY: J1.39(12V_SB) J2.39(12V_SB) J3.39(12V_SB) J4.39(12V_SB) J5.39(12V_SB) J6.39(12V_SB) R4.2 R16.2 R18.2 R40.2 R42.2 R44.2 R62.2 R64.2 R66.2 R68.2 R70.2 R72.2 R74.2 R76.2 R78.2 R80.2 R82.2 R84.2
B1_PSU_ALERT_N: J7.S4 U4.2(OUT)
B2_PSU_ALERT_N: J7.S9 U4.4(OUT)
B3_PSU_ALERT_N: J8.S4 U4.6(OUT)
B4_PSU_ALERT_N: J8.S9 U4.8(OUT)
B5_PSU_ALERT_N: J9.S4 U4.10(OUT)
B6_PSU_ALERT_N: J9.S9 U4.12(OUT)
B7_PSU_ALERT_N: J10.S4 U5.2(OUT)
B8_PSU_ALERT_N: J10.S9 U5.4(OUT)
B9_PSU_ALERT_N: J11.S4 U5.6(OUT)
B10_PSU_ALERT_N: J11.S9 U5.8(OUT)
B11_PSU_ALERT_N: J12.S4 U5.10(OUT)
B12_PSU_ALERT_N: J12.S9 U5.12(OUT)
B13_PSU_ALERT_N: J13.S4 U6.2(OUT)
B14_PSU_ALERT_N: J13.S9 U6.4(OUT)
B15_PSU_ALERT_N: J14.S4 U6.6(OUT)
B16_PSU_ALERT_N: J14.S9 U6.8(OUT)
B17_PSU_ALERT_N: J15.S4 U6.10(OUT)
B18_PSU_ALERT_N: J15.S9 U6.12(OUT)
B19_PSU_ALERT_N: J16.S4 U7.2(OUT)
B20_PSU_ALERT_N: J16.S9 U7.4(OUT)
B21_PSU_ALERT_N: J17.S4 U7.6(OUT)
B22_PSU_ALERT_N: J17.S9 U7.8(OUT)
B23_PSU_ALERT_N: J18.S4 U7.10(OUT)
B24_PSU_ALERT_N: J18.S9 U7.12(OUT)
CM_PWR_CTL_IN: J26.B78(HSOP15+) J33.1
FAN1_TACH: J20.1 J25.B27(HSOP3+) R142.1
FAN2_TACH: J20.4 J25.B28(HSOP3-) R143.1
FAN3_TACH: J20.7 J25.B29(GND10) R144.1
FAN4_TACH: J20.10 J25.A26(HSIP2-) R145.1
FAN5_TACH: J20.11 J25.A27(GND42) R146.1
FAN6_TACH: J20.14 J25.A28(GND43) R147.1
FAN_PWM: J20.17 J20.20 J25.A30(HSIP3-) R140.1 R141.1
FRU_A0: R34.2 R37.2 U1.1(E0)
FRU_A1: R35.2 R38.2 U1.2(E1)
FRU_A2: R36.2 R39.2 U1.3(E2)
FRU_WP: R41.2 U1.7(W\C\)
I2C_PDB_SCL: J25.B10(3.3VAUX) U1.6(SCL)
I2C_PDB_SDA: J25.B11(WAKE_N) U1.5(SDA)
I2C_PSU1_SCL: J1.35(SCL) J2.35(SCL) J26.B42(HSOP6-)
I2C_PSU1_SDA: J1.33(SDA) J2.33(SDA) J26.B43(GND16)
I2C_PSU2_SCL: J3.35(SCL) J4.35(SCL) J26.B10(3.3VAUX)
I2C_PSU2_SDA: J3.33(SDA) J4.33(SDA) J26.B11(WAKE_N)
I2C_PSU3_SCL: J5.35(SCL) J6.35(SCL) J25.A32(RSVD5)
I2C_PSU3_SDA: J5.33(SDA) J6.33(SDA) J25.A33(RSVD6)
LAN1_P1_N: J26.A73(HSIP13-) J29.2(TCT)
LAN1_P1_P: J26.A72(HSIP13+) J29.1(TD+)
LAN1_P2_N: J26.A76(HSIP14) J29.6(RD-)
LAN1_P2_P: J26.A75(GND64) J29.3(TD-)
LAN1_P3_N: J26.B73(GND31) J29.5(RCT)
LAN1_P3_P: J26.B72(GND30) J29.4(RD+)
LAN1_P4_N: J26.B76(GND32) J29.8
LAN1_P4_P: J26.B75(HSOP14-) J29.7
LAN2_P1_N: J25.B3(12V_3) J28.2(TCT)
LAN2_P1_P: J25.B2(12V_2) J28.1(TD+)
LAN2_P2_N: J25.B6(SMDATA) J28.6(RD-)
LAN2_P2_P: J25.B5(SMCLK) J28.3(TD-)
LAN2_P3_N: J25.A4(GND35) J28.5(RCT)
LAN2_P3_P: J25.A3(12V_5) J28.4(RD+)
LAN2_P4_N: J25.A7(JTAG4) J28.8
LAN2_P4_P: J25.A6(JTAG3) J28.7
MATE_A1: J25.A1(PRSNT1_N) J26.B81(PRSNT2_N-4)
PHLOSS: J1.25(TACH) J2.25(TACH) J3.25(TACH) J4.25(TACH) J5.25(TACH) J6.25(TACH) R161.2
POWER_SW1_PWR_CTR_12V: J25.A11(PERST#) J32.1
POWER_SW2_PWR_CTR_12V: J25.A10(3.3V_3) J31.1
POWER_SW3_PWR_CTR_12V: J25.A9(3.3V_2) J30.1
PSU1_AC_OK: J1.27(VIN_GOOD) J26.B45(HSOP7+)
PSU1_AD0: J1.38(PS_A0) R12.1
PSU1_CSAHRE: J1.28(CSHARE) R134.1
PSU1_DC_OK: J1.37(POK) J26.A45(GND50)
PSU1_PS_KILL: J1.30(PS_KILL) R43.1 R62.1 R63.1
PSU1_PS_ON_N: J1.29(-PS_ON) R49.2
PSU1_REMOTE_N: J1.26(REMOTE SENSE-) R5.1 R87.1 R113.1
PSU1_REMOTE_P: J1.40(REMOTE SENSE+) R1.1 R86.1 R110.1
PSU1_REMOTE_R2_N: R112.1 R113.2
PSU1_REMOTE_R2_P: R110.2 R111.1
PSU1_REMOTE_R_N: R87.2 R89.1
PSU1_REMOTE_R_P: R86.2 R88.1
PSU1_RESET: J1.31(RESET) R45.1 R64.1 R65.1
PSU1_RETURN: J1.36(RETURN) R9.1
PSU2_AC_OK: J2.27(VIN_GOOD) J26.B46(HSOP7-)
PSU2_AD0: J2.38(PS_A0) R4.1 R8.1
PSU2_CSAHRE: J2.28(CSHARE) R135.1
PSU2_DC_OK: J2.37(POK) J26.A46(GND51)
PSU2_PS_KILL: J2.30(PS_KILL) R46.1 R66.1 R67.1
PSU2_PS_ON_N: J2.29(-PS_ON) R50.2
PSU2_REMOTE_N: J2.26(REMOTE SENSE-) R7.1 R93.1 R117.1
PSU2_REMOTE_P: J2.40(REMOTE SENSE+) R3.1 R90.1 R114.1
PSU2_REMOTE_R2_N: R116.1 R117.2
PSU2_REMOTE_R2_P: R114.2 R115.1
PSU2_REMOTE_R_N: R91.1 R93.2
PSU2_REMOTE_R_P: R90.2 R92.1
PSU2_RESET: J2.31(RESET) R47.1 R68.1 R69.1
PSU2_RETURN: J2.36(RETURN) R11.1
PSU3_AC_OK: J3.27(VIN_GOOD) J26.B47(GND18)
PSU3_AD0: J3.38(PS_A0) R13.1
PSU3_CSAHRE: J3.28(CSHARE) R136.1
PSU3_DC_OK: J3.37(POK) J26.A47(HSIP7+)
PSU3_PS_KILL: J3.30(PS_KILL) R48.1 R70.1 R71.1
PSU3_PS_ON_N: J3.29(-PS_ON) R51.2
PSU3_REMOTE_N: J3.26(REMOTE SENSE-) R6.1 R97.1 R121.1
PSU3_REMOTE_P: J3.40(REMOTE SENSE+) R2.1 R94.1 R118.1
PSU3_REMOTE_R2_N: R120.1 R121.2
PSU3_REMOTE_R2_P: R118.2 R119.1
PSU3_REMOTE_R_N: R95.1 R97.2
PSU3_REMOTE_R_P: R94.2 R96.1
PSU3_RESET: J3.31(RESET) R55.1 R72.1 R73.1
PSU3_RETURN: J3.36(RETURN) R10.1
PSU4_AC_OK: J4.27(VIN_GOOD) J26.B48(PRSNT2_N-3)
PSU4_AD0: J4.38(PS_A0) R16.1 R21.1
PSU4_CSAHRE: J4.28(CSHARE) R137.1
PSU4_DC_OK: J4.37(POK) J26.A48(HSIP7-)
PSU4_PS_KILL: J4.30(PS_KILL) R56.1 R74.1 R75.1
PSU4_PS_ON_N: J4.29(-PS_ON) R52.2
PSU4_REMOTE_N: J4.26(REMOTE SENSE-) R20.1 R109.1 R125.1
PSU4_REMOTE_P: J4.40(REMOTE SENSE+) R15.1 R106.1 R122.1
PSU4_REMOTE_R2_N: R124.1 R125.2
PSU4_REMOTE_R2_P: R122.2 R123.1
PSU4_REMOTE_R_N: R107.1 R109.2
PSU4_REMOTE_R_P: R106.2 R108.1
PSU4_RESET: J4.31(RESET) R57.1 R76.1 R77.1
PSU4_RETURN: J4.36(RETURN) R25.1
PSU5_AC_OK: J5.27(VIN_GOOD) J26.B49(GND19)
PSU5_AD0: J5.38(PS_A0) R27.1
PSU5_CSAHRE: J5.28(CSHARE) R138.1
PSU5_DC_OK: J5.37(POK) J26.A49(GND52)
PSU5_PS_KILL: J5.30(PS_KILL) R58.1 R78.1 R79.1
PSU5_PS_ON_N: J5.29(-PS_ON) R53.2
PSU5_REMOTE_N: J5.26(REMOTE SENSE-) R19.1 R105.1 R129.1
PSU5_REMOTE_P: J5.40(REMOTE SENSE+) R14.1 R102.1 R126.1
PSU5_REMOTE_R2_N: R128.1 R129.2
PSU5_REMOTE_R2_P: R126.2 R127.1
PSU5_REMOTE_R_N: R103.1 R105.2
PSU5_REMOTE_R_P: R102.2 R104.1
PSU5_RESET: J5.31(RESET) R59.1 R80.1 R81.1
PSU5_RETURN: J5.36(RETURN) R24.1
PSU6_AC_OK: J6.27(VIN_GOOD) J26.B50(HSOP8+)
PSU6_AD0: J6.38(PS_A0) R18.1 R23.1
PSU6_CSAHRE: J6.28(CSHARE) R139.1
PSU6_DC_OK: J6.37(POK) J26.A50(RSVD7)
PSU6_PS_KILL: J6.30(PS_KILL) R60.1 R82.1 R83.1
PSU6_PS_ON_N: J6.29(-PS_ON) R54.2
PSU6_REMOTE_N: J6.26(REMOTE SENSE-) R22.1 R101.1 R133.1
PSU6_REMOTE_P: J6.40(REMOTE SENSE+) R17.1 R98.1 R130.1
PSU6_REMOTE_R2_N: R132.1 R133.2
PSU6_REMOTE_R2_P: R130.2 R131.1
PSU6_REMOTE_R_N: R99.1 R101.2
PSU6_REMOTE_R_P: R98.2 R100.1
PSU6_RESET: J6.31(RESET) R61.1 R84.1 R85.1
PSU6_RETURN: J6.36(RETURN) R26.1
PSU_ALERT_N: J1.32(ALERT) J2.32(ALERT) J3.32(ALERT) J4.32(ALERT) J5.32(ALERT) J6.32(ALERT) J25.A80(HSIP15+) R162.2 R163.2 U4.1(IN) U4.3(IN) U4.5(IN) U4.9(IN) U4.11(IN) U4.13(IN) U5.1(IN) U5.3(IN) U5.5(IN) U5.9(IN) U5.11(IN) U5.13(IN) U6.1(IN) U6.3(IN) U6.5(IN) U6.9(IN) U6.11(IN) U6.13(IN) U7.1(IN) U7.3(IN) U7.5(IN) U7.9(IN) U7.11(IN) U7.13(IN)
PSU_CSAHRE: R134.2 R135.2 R136.2 R137.2 R138.2 R139.2
T1_BLAD1_EN: J7.S3 J26.A30(HSIP3-)
T1_BLAD1_RXD: J7.S2 J26.A42(GND49)
T1_BLAD1_TXD: J7.S1 J26.A43(HSIP6+)
T1_BLAD2_EN: J26.A31(GND44) R163.1
T1_BLAD2_RXD: J7.S6 J26.A35(HSIP4+)
T1_BLAD2_TXD: J7.S5 J26.A36(HSIP4-)
T1_BLAD3_EN: J7.S10 J26.A32(RSVD5)
T1_BLAD3_RXD: J7.S11 J26.A37(GND46)
T1_BLAD3_TXD: J7.S12 J26.A38(GND47)
T1_BLAD4_RXD: J7.S7 J26.A40(HSIP5-)
T1_BLAD4_TXD: J7.S8 J26.A41(GND48)
T2_BLAD1_EN: J8.S3 J26.B27(HSOP3+)
T2_BLAD1_RXD: J8.S2 J26.B32(GND11)
T2_BLAD1_TXD: J8.S1 J26.B33(HSOP4+)
T2_BLAD2_RXD: J8.S6 J26.B34(HSOP4-)
T2_BLAD2_TXD: J8.S5 J26.B35(GND12)
T2_BLAD3_EN: J8.S10 J26.B29(GND10)
T2_BLAD3_RXD: J8.S11 J26.B37(HSOP5+)
T2_BLAD3_TXD: J8.S12 J26.B38(HSOP5-)
T2_BLAD4_RXD: J8.S7 J26.B39(GND14)
T2_BLAD4_TXD: J8.S8 J26.B40(GND15)
T3_BLAD1_EN: J9.S3 J26.A15(GND37)
T3_BLAD1_RXD: J9.S2 J26.A20(GND39)
T3_BLAD1_TXD: J9.S1 J26.A21(HSIP1+)
T3_BLAD2_RXD: J9.S6 J26.A22(HSIP1-)
T3_BLAD2_TXD: J9.S5 J26.A23(GND40)
T3_BLAD3_EN: J9.S10 J26.A17(HSIP0-)
T3_BLAD3_RXD: J9.S11 J26.A25(HSIP2+)
T3_BLAD3_TXD: J9.S12 J26.A26(HSIP2-)
T3_BLAD4_RXD: J9.S7 J26.A27(GND42)
T3_BLAD4_TXD: J9.S8 J26.A28(GND43)
T4_BLAD1_EN: J10.S3 J26.B12(RSVD1)
T4_BLAD1_RXD: J10.S2 J26.B17(PRSNT2_N-1)
T4_BLAD1_TXD: J10.S1 J26.B18(GND5)
T4_BLAD2_RXD: J10.S6 J26.B19(HSOP1+)
T4_BLAD2_TXD: J10.S5 J26.B20(HSOP1-)
T4_BLAD3_EN: J10.S10 J26.B14(HSOP0+)
T4_BLAD3_RXD: J10.S11 J26.B22(GND7)
T4_BLAD3_TXD: J10.S12 J26.B23(HSOP2+)
T4_BLAD4_RXD: J10.S7 J26.B24(HSOP2-)
T4_BLAD4_TXD: J10.S8 J26.B25(GND8)
T5_BLAD1_EN: J11.S3 J25.A81(HSIP15-)
T5_BLAD1_RXD: J11.S2 J26.A5(JTAG2)
T5_BLAD1_TXD: J11.S1 J26.A6(JTAG3)
T5_BLAD2_RXD: J11.S6 J26.A8(JTAG5)
T5_BLAD2_TXD: J11.S5 J26.A9(3.3V_2)
T5_BLAD3_EN: J11.S10 J26.A2(12V_4)
T5_BLAD3_RXD: J11.S11 J26.A10(3.3V_3)
T5_BLAD3_TXD: J11.S12 J26.A11(PERST#)
T5_BLAD4_RXD: J11.S7 J26.A12(GND36)
T5_BLAD4_TXD: J11.S8 J26.A13(REFCLK+)
T6_BLAD1_EN: J12.S3 J25.B76(GND32)
T6_BLAD1_RXD: J12.S2 J25.B81(PRSNT2_N-4)
T6_BLAD1_TXD: J12.S1 J25.B82(RSVD3)
T6_BLAD2_RXD: J12.S6 J26.B2(12V_2)
T6_BLAD2_TXD: J12.S5 J26.B3(12V_3)
T6_BLAD3_EN: J12.S10 J25.B78(HSOP15+)
T6_BLAD3_RXD: J12.S11 J26.B5(SMCLK)
T6_BLAD3_TXD: J12.S12 J26.B6(SMDATA)
T6_BLAD4_RXD: J12.S7 J26.B7(GND2)
T6_BLAD4_TXD: J12.S8 J26.B8(3.3V_1)
T7_BLAD1_EN: J13.S3 J25.A65(HSIP11-)
T7_BLAD1_RXD: J13.S2 J25.A70(GND61)
T7_BLAD1_TXD: J13.S1 J25.A71(GND62)
T7_BLAD2_RXD: J13.S6 J25.A72(HSIP13+)
T7_BLAD2_TXD: J13.S5 J25.A73(HSIP13-)
T7_BLAD3_EN: J13.S10 J25.A67(RSVD8)
T7_BLAD3_RXD: J13.S11 J25.A75(GND64)
T7_BLAD3_TXD: J13.S12 J25.A76(HSIP14)
T7_BLAD4_RXD: J13.S7 J25.A77(HSIP14-)
T7_BLAD4_TXD: J13.S8 J25.A78(GND65)
T8_BLAD1_EN: J14.S3 J25.B61(GND25)
T8_BLAD1_RXD: J14.S2 J25.B66(HSOP12+)
T8_BLAD1_TXD: J14.S1 J25.B67(HSOP12-)
T8_BLAD2_RXD: J14.S6 J25.B68(GND28)
T8_BLAD2_TXD: J14.S5 J25.B69(GND29)
T8_BLAD3_EN: J14.S10 J25.B63(HSOP11-)
T8_BLAD3_RXD: J14.S11 J25.B71(HSOP13-)
T8_BLAD3_TXD: J14.S12 J25.B72(GND30)
T8_BLAD4_RXD: J14.S7 J25.B73(GND31)
T8_BLAD4_TXD: J14.S8 J25.B74(HSOP14+)
T9_BLAD1_EN: J15.S3 J25.A50(RSVD7)
T9_BLAD1_RXD: J15.S2 J25.A55(GND55)
T9_BLAD1_TXD: J15.S1 J25.A56(HSIP9+)
T9_BLAD2_RXD: J15.S6 J25.A57(HSIP9-)
T9_BLAD2_TXD: J15.S5 J25.A58(GND56)
T9_BLAD3_EN: J15.S10 J25.A52(HSIP8+)
T9_BLAD3_RXD: J15.S11 J25.A60(HSIP10+)
T9_BLAD3_TXD: J15.S12 J25.A61(HSIP10-)
T9_BLAD4_RXD: J15.S7 J25.A62(GND58)
T9_BLAD4_TXD: J15.S8 J25.A63(GND59)
T10_BLAD1_EN: J16.S3 J25.B46(HSOP7-)
T10_BLAD1_RXD: J16.S2 J25.B51(HSOP8-)
T10_BLAD1_TXD: J16.S1 J25.B52(GND20)
T10_BLAD2_RXD: J16.S6 J25.B53(GND21)
T10_BLAD2_TXD: J16.S5 J25.B54(HSOP9+)
T10_BLAD3_EN: J16.S10 J25.B48(PRSNT2_N-3)
T10_BLAD3_RXD: J16.S11 J25.B56(GND22)
T10_BLAD3_TXD: J16.S12 J25.B57(GND23)
T10_BLAD4_RXD: J16.S7 J25.B58(HSOP10+)
T10_BLAD4_TXD: J16.S8 J25.B59(HSOP10-)
T11_BLAD1_EN: J17.S3 J25.A35(HSIP4+)
T11_BLAD1_RXD: J17.S2 J25.A40(HSIP5-)
T11_BLAD1_TXD: J17.S1 J25.A41(GND48)
T11_BLAD2_RXD: J17.S6 J25.A42(GND49)
T11_BLAD2_TXD: J17.S5 J25.A43(HSIP6+)
T11_BLAD3_EN: J17.S10 J25.A37(GND46)
T11_BLAD3_RXD: J17.S11 J25.A45(GND50)
T11_BLAD3_TXD: J17.S12 J25.A46(GND51)
T11_BLAD4_RXD: J17.S7 J25.A47(HSIP7+)
T11_BLAD4_TXD: J17.S8 J25.A48(HSIP7-)
T12_BLAD1_EN: J18.S3 J25.B31(PRSNT2_N-2)
T12_BLAD1_RXD: J18.S2 J25.B36(GND13)
T12_BLAD1_TXD: J18.S1 J25.B37(HSOP5+)
T12_BLAD2_RXD: J18.S6 J25.B38(HSOP5-)
T12_BLAD2_TXD: J18.S5 J25.B39(GND14)
T12_BLAD3_EN: J18.S10 J25.B33(HSOP4+)
T12_BLAD3_RXD: J18.S11 J25.B41(HSOP6+)
T12_BLAD3_TXD: J18.S12 J25.B42(HSOP6-)
T12_BLAD4_RXD: J18.S7 J25.B43(GND16)
T12_BLAD4_TXD: J18.S8 J25.B44(GND17)
TP_T1_BLAD4_EN: J26.A33(RSVD6)
TP_T2_BLAD2_EN: J26.B28(HSOP3-)
TP_T2_BLAD4_EN: J26.B30(RSVD2)
TP_T3_BLAD2_EN: J26.A16(HSIP0+)
TP_T3_BLAD4_EN: J26.A18(GND38)
TP_T4_BLAD2_EN: J26.B13(GND3)
TP_T4_BLAD4_EN: J26.B15(HSOP0-)
TP_T5_BLAD2_EN: J25.A82(GND67)
TP_T5_BLAD4_EN: J26.A3(12V_5)
TP_T6_BLAD2_EN: J25.B77(GND33)
TP_T6_BLAD4_EN: J25.B79(HSOP15-)
TP_T7_BLAD2_EN: J25.A66(GND60)
TP_T7_BLAD4_EN: J25.A68(HSIP12+)
TP_T8_BLAD2_EN: J25.B62(HSOP11+)
TP_T8_BLAD4_EN: J25.B64(GND26)
TP_T9_BLAD2_EN: J25.A51(GND53)
TP_T9_BLAD4_EN: J25.A53(HSIP8-)
TP_T10_BLAD2_EN: J25.B47(GND18)
TP_T10_BLAD4_EN: J25.B49(GND19)
TP_T11_BLAD2_EN: J25.A36(HSIP4-)
TP_T11_BLAD4_EN: J25.A38(GND47)
TP_T12_BLAD2_EN: J25.B32(GND11)
TP_T12_BLAD4_EN: J25.B34(HSOP4-)
